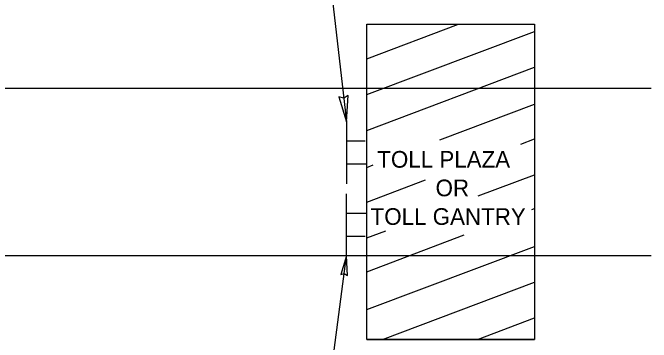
# Model space of a CAD drawing. Extents: x 46672 to 47298, y 5424 to 5742.
# Drawn here: x 47173.2 to 47280.2, y 5614.1 to 5669.4 of the extents above; entities that cross this region are included whole.
import ezdxf

# ---------------------------------------------------------------- set-up
doc = ezdxf.new("R2010")
doc.units = 0
for name, color, linetype in [('GSBWFill', 7, 'Continuous'), ('SheetBorder_dp', 7, 'Continuous'), ('SheetLines_dp', 7, 'Continuous'), ('TextMisc', 7, 'Continuous')]:
    doc.layers.add(name, color=color, linetype=linetype)

msp = doc.modelspace()

# ---------------------------------------------------------------- linework, layer by layer
at = {"layer": 'GSBWFill'}
for p, q in [((47232.52, 5667.51), (47260.65, 5667.51)), ((47232.52, 5614.56), (47232.52, 5667.51)), ((47232.52, 5661.67), (47247.89, 5667.47)), ((47260.65, 5667.51), (47260.65, 5614.56)), ((47232.52, 5655.66), (47260.65, 5666.27)), ((47232.52, 5649.65), (47260.65, 5660.26)), ((47010.15, 5656.76), (47280.21, 5656.76)), ((47244.79, 5648.08), (47260.65, 5654.06)), ((47258.36, 5647.37), (47260.65, 5648.23)), ((47232.52, 5643.45), (47233.6, 5643.86)), ((47251.21, 5638.66), (47260.65, 5642.22)), ((47232.52, 5637.62), (47242.38, 5641.34)), ((47260.21, 5636.38), (47260.65, 5636.55)), ((47232.52, 5631.61), (47235.73, 5632.82)), ((47232.52, 5625.94), (47248.88, 5632.11)), ((47232.52, 5619.59), (47260.65, 5630.19)), ((47010.15, 5628.64), (47280.21, 5628.64)), ((47235.14, 5614.56), (47260.65, 5624.18)), ((47251.08, 5614.56), (47260.65, 5618.17)), ((47232.52, 5614.56), (47260.65, 5614.56)), ((47260.65, 5614.56), (47232.52, 5614.56))]:
    msp.add_line(p, q, dxfattribs=at)
at = {"layer": 'SheetLines_dp'}
for p, q in [((47223.2, 5702.26), (47229.14, 5651.07)), ((47223.2, 5583.15), (47229.14, 5628.63))]:
    msp.add_line(p, q, dxfattribs=at)
for points in [[(47229.14, 5651.07), (47229.38, 5655.5), (47228.67, 5655.09), (47227.86, 5655.31)], [(47229.14, 5628.63), (47228.15, 5625.46), (47228.74, 5625.62), (47229.29, 5625.31)]]:
    msp.add_lwpolyline(points, close=True, dxfattribs=at)
at = {"layer": 'TextMisc'}
for p, q in [((47229.14, 5651.07), (47229.14, 5640.68)), ((47232.26, 5647.85), (47229.14, 5647.85)), ((47232.48, 5644), (47229.14, 5644)), ((47229.14, 5628.63), (47229.14, 5639.02)), ((47232.48, 5635.7), (47229.14, 5635.7)), ((47232.26, 5631.85), (47229.14, 5631.85))]:
    msp.add_line(p, q, dxfattribs=at)

# ---------------------------------------------------------------- texts
at = {"layer": 'SheetBorder_dp'}
for s, height, p in [('TOLL PLAZA', 2.8, (47234.29, 5643.4)), ('OR', 2.8, (47244.06, 5638.6)), ('TOLL GANTRY', 2.8004, (47233.17, 5633.8))]:
    msp.add_text(s, height=height, dxfattribs=at).set_placement(p)

doc.saveas('drawing.dxf')
